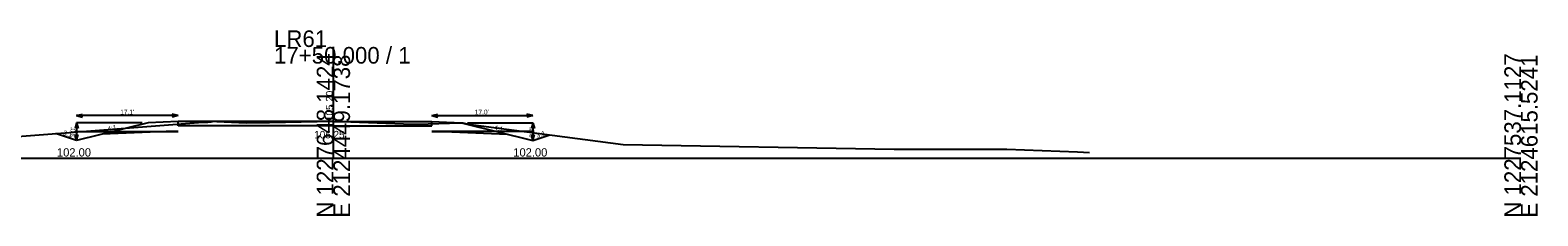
# Model space of a CAD drawing. Extents: x -26 to 1403, y -10 to 9574.
# Drawn here: x 1148.9 to 1402.8, y 7490.3 to 7521.6 of the extents above; entities that cross this region are included whole.
import ezdxf

# ---------------------------------------------------------------- set-up
doc = ezdxf.new("R2010")
doc.units = 0
for name, color, linetype in [('XS_CELL', 7, 'Continuous'), ('XS_P_FINISHED_GRADE', 7, 'Continuous'), ('XS_P_FINISHED_GRADE_ELEV_TX', 7, 'Continuous'), ('XS_P_SUBGRADE_GRANULAR', 7, 'Continuous'), ('XS_P_SUBGRADE_PAVEMENT', 7, 'Continuous'), ('XS_P_TX_CLEARZONE', 7, 'Continuous'), ('XS_P_TX_DCH', 7, 'Continuous'), ('XS_P_TX_FS_BS', 7, 'Continuous'), ('XS_X_GROUND', 7, 'Continuous'), ('XS_X_GROUND_TX', 7, 'Continuous')]:
    doc.layers.add(name, color=color, linetype=linetype)

msp = doc.modelspace()

# ---------------------------------------------------------------- linework, layer by layer
at = {"layer": 'XS_CELL'}
for p, q in [((1200, 7500), (1200, 7518.76)), ((1000, 7500), (1200, 7500)), ((1200, 7500), (1400, 7500))]:
    msp.add_line(p, q, dxfattribs=at)
at = {"layer": 'XS_P_FINISHED_GRADE'}
for p, q in [((1168.81, 7506), (1156.75, 7503)), ((1173.84, 7506.2), (1168.81, 7506)), ((1200, 7506.2), (1173.84, 7506.2)), ((1200, 7506.2), (1216.6, 7506.2)), ((1216.6, 7506.2), (1221.6, 7506)), ((1221.6, 7506), (1233.6, 7503)), ((1156.75, 7503), (1153.22, 7504.17)), ((1233.6, 7503), (1236.45, 7503.95))]:
    msp.add_line(p, q, dxfattribs=at)
at = {"layer": 'XS_P_SUBGRADE_GRANULAR'}
for p, q in [((1156.55, 7504.5), (1173.84, 7504.5)), ((1171.84, 7504.5), (1161.05, 7504.07)), ((1173.84, 7504.5), (1171.84, 7504.5)), ((1233.8, 7504.5), (1216.6, 7504.5)), ((1216.6, 7504.5), (1218.6, 7504.5)), ((1218.6, 7504.5), (1229.31, 7504.07))]:
    msp.add_line(p, q, dxfattribs=at)
at = {"layer": 'XS_P_SUBGRADE_PAVEMENT'}
for p, q in [((1173.84, 7505.45), (1173.84, 7506.2)), ((1200, 7505.45), (1173.84, 7505.45)), ((1200, 7505.45), (1216.6, 7505.45)), ((1216.6, 7505.45), (1216.6, 7506.2))]:
    msp.add_line(p, q, dxfattribs=at)
at = {"layer": 'XS_P_TX_CLEARZONE'}
for p, q in [((1156.75, 7506), (1156.5, 7505)), ((1156.75, 7507.2), (1157.76, 7507.45)), ((1156.75, 7507.2), (1157.76, 7506.95)), ((1173.84, 7507.2), (1156.75, 7507.2)), ((1156.75, 7506), (1157, 7505)), ((1156.75, 7506), (1156.75, 7503)), ((1167.81, 7506), (1156.75, 7506)), ((1173.84, 7507.2), (1172.83, 7507.45)), ((1173.84, 7507.2), (1172.83, 7506.95)), ((1216.6, 7507.2), (1217.6, 7507.45)), ((1216.6, 7507.2), (1217.6, 7506.95)), ((1216.6, 7507.2), (1233.6, 7507.2)), ((1222.6, 7506), (1233.6, 7506)), ((1233.6, 7507.2), (1232.6, 7507.45)), ((1233.6, 7507.2), (1232.6, 7506.95)), ((1233.6, 7506), (1233.35, 7505)), ((1233.6, 7506), (1233.6, 7503)), ((1233.6, 7506), (1233.85, 7505)), ((1156.75, 7503), (1156.5, 7504)), ((1156.75, 7503), (1157, 7504)), ((1233.6, 7503), (1233.35, 7504)), ((1233.6, 7503), (1233.85, 7504))]:
    msp.add_line(p, q, dxfattribs=at)
at = {"layer": 'XS_X_GROUND'}
for p, q in [((1121.17, 7501.69), (1177.99, 7506.1)), ((1177.99, 7506.1), (1178.87, 7506.08)), ((1178.87, 7506.08), (1179.44, 7506.14)), ((1179.44, 7506.14), (1179.85, 7506.24)), ((1179.85, 7506.24), (1180.4, 7506.21)), ((1180.4, 7506.21), (1185.29, 7505.96)), ((1185.29, 7505.96), (1189.25, 7506.04)), ((1189.25, 7506.04), (1199.98, 7506.25)), ((1199.98, 7506.25), (1211.82, 7505.83)), ((1211.82, 7505.83), (1214.19, 7505.75)), ((1214.19, 7505.75), (1221.37, 7505.97)), ((1221.37, 7505.97), (1221.82, 7505.98)), ((1221.82, 7505.98), (1222.78, 7505.76)), ((1222.78, 7505.76), (1248.78, 7502.33)), ((1248.78, 7502.33), (1294.43, 7501.56)), ((1294.43, 7501.56), (1313.44, 7501.52)), ((1313.44, 7501.52), (1325.29, 7501.12)), ((1325.29, 7501.12), (1327.35, 7501))]:
    msp.add_line(p, q, dxfattribs=at)

# ---------------------------------------------------------------- texts
at = {"layer": 'XS_CELL'}
for s, p in [('LR61', (1190, 7518.76)), ('17+50.000 / 1', (1190, 7515.96))]:
    msp.add_text(s, height=2.8, dxfattribs=at).set_placement(p)
for s, p in [('N 1227648.1424', (1200, 7490)), ('E 2124449.1738', (1202.8, 7490)), ('N 1227537.1127', (1400, 7490)), ('E 2124615.5241', (1402.8, 7490))]:
    msp.add_text(s, height=2.8, rotation=90, dxfattribs=at).set_placement(p)
at = {"layer": 'XS_P_FINISHED_GRADE_ELEV_TX'}
msp.add_text('105.20', height=1.25, rotation=90, dxfattribs=at).set_placement((1199.99, 7506.28))
at = {"layer": 'XS_P_TX_CLEARZONE'}
for s, p in [("17.1'", (1164.1, 7507.4)), ("17.0'", (1223.82, 7507.4))]:
    msp.add_text(s, height=0.8, dxfattribs=at).set_placement(p)
for p in [(1156.55, 7503.48), (1233.8, 7503.48)]:
    msp.add_text("3.0'", height=0.8, rotation=90, dxfattribs=at).set_placement(p)
at = {"layer": 'XS_P_TX_DCH'}
for p in [(1153.45, 7500.3), (1230.3, 7500.3)]:
    msp.add_text('102.00', height=1.4, dxfattribs=at).set_placement(p)
at = {"layer": 'XS_P_TX_FS_BS'}
for s, rotation, p in [('4:1', 13.9701, (1162.07, 7504.53)), ('4:1', 345.9674, (1226.99, 7504.86)), ('3:1', 341.6494, (1154.4, 7503.99)), ('3:1', 18.4303, (1234.32, 7503.45))]:
    msp.add_text(s, height=0.8, rotation=rotation, dxfattribs=at).set_placement(p)
at = {"layer": 'XS_X_GROUND_TX'}
msp.add_text('105.25', height=1.25, rotation=360, dxfattribs=at).set_placement((1196.77, 7503.37))

doc.saveas('drawing.dxf')
